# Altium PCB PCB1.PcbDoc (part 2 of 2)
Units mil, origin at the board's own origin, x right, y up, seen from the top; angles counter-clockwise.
Board outline 3035 x 2265 mil, 2 copper layers (Top Layer, Bottom Layer); 66 components, 70 nets, 274 pads, 24 vias.
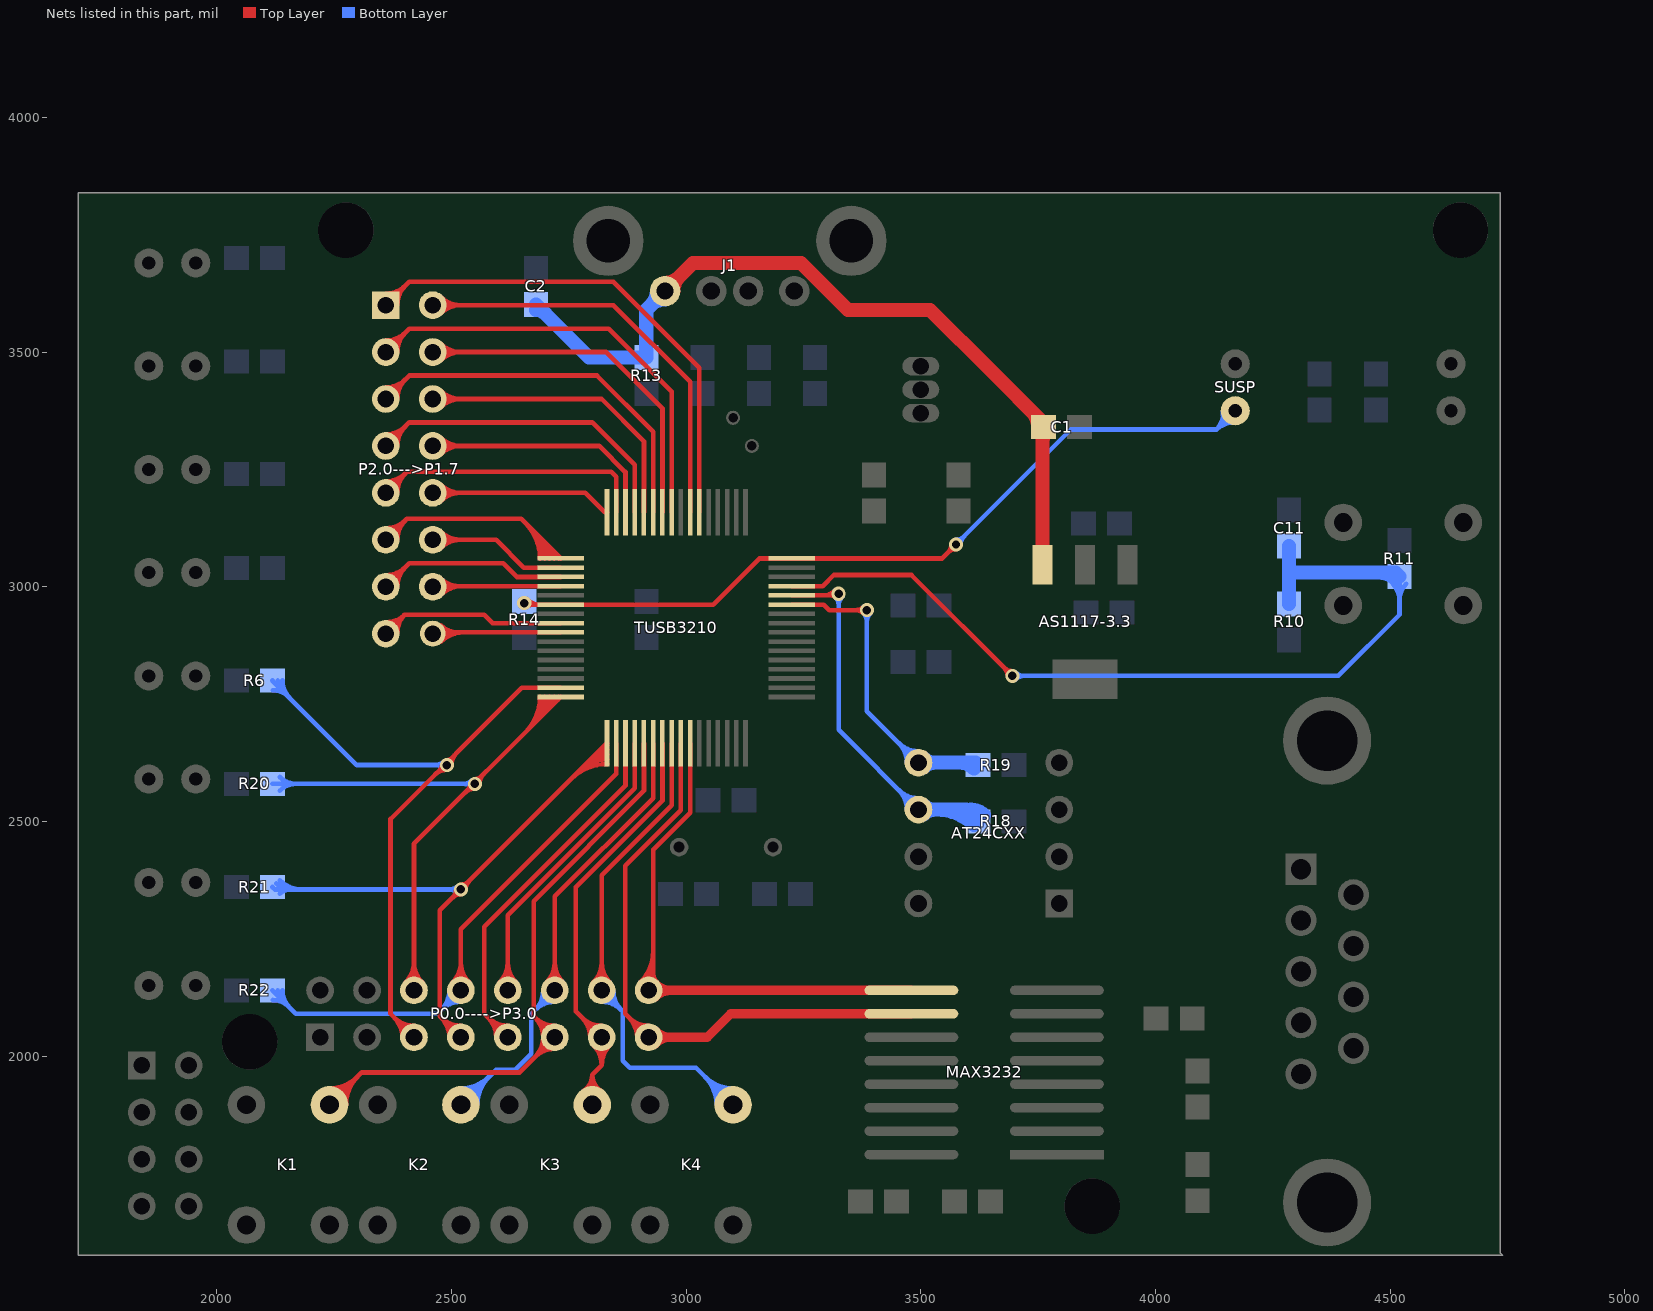
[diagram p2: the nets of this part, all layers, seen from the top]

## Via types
v1: diameter 30, hole 18, Top Layer to Bottom Layer, 24 vias

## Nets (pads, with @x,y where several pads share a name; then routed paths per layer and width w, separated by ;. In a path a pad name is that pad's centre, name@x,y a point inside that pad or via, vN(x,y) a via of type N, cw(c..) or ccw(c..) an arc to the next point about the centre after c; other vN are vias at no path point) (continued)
P0_4: P0.0---->P3.0.5 R6.1 TUSB3210.47 | length 2282.5
  Top Layer w10: P0.0---->P3.0.5@2420,2040 2370,2090 2370,2505 2649.68,2784.68 TUSB3210.47@2732.87,2784.68 ; 2378.13,2081.87 cw(c2336.26,2040) P0.0---->P3.0.5@2395.47,2040 ; 2378.13,2081.87 ccw(c2420,2123.74) P0.0---->P3.0.5@2420,2064.53 ; 2378.13,2081.87 cw(c2336.26,2040) P0.0---->P3.0.5@2395.47,2040 ; 2378.13,2081.87 ccw(c2420,2123.74) P0.0---->P3.0.5@2420,2064.53 ; 2378.13,2081.87 ccw(c2420,2123.74) P0.0---->P3.0.5@2420,2064.53 ; 2378.13,2081.87 cw(c2336.26,2040) P0.0---->P3.0.5@2395.47,2040 ; 2395.2,2064.8 cw(c2370.4,2040) P0.0---->P3.0.5@2405.47,2040 ; 2395.2,2064.8 ccw(c2420,2089.6) P0.0---->P3.0.5@2420,2054.53 ; 2395.2,2064.8 cw(c2370.4,2040) P0.0---->P3.0.5@2405.47,2040 ; 2395.2,2064.8 ccw(c2420,2089.6) P0.0---->P3.0.5@2420,2054.53 ; 2395.2,2064.8 ccw(c2420,2089.6) P0.0---->P3.0.5@2420,2054.53 ; 2395.2,2064.8 cw(c2370.4,2040) P0.0---->P3.0.5@2405.47,2040 ; 2464.39,2599.39 cw(c2490,2573.79) 2490,2610 ccw(c2490,2573.79) 2464.39,2599.39 ; 2476.46,2611.46 ccw(c2467.93,2620) 2480,2620 cw(c2467.93,2620) 2476.46,2611.46 ; v1@2490,2630 ccw(c2490,2642.07) 2498.54,2633.54 cw(c2490,2642.07) v1@2490,2630 ; v1@2500,2620 cw(c2536.21,2620) 2510.61,2645.61 ccw(c2536.21,2620) v1@2500,2620
  Bottom Layer w10: R6.1@2118.39,2800 2298.39,2620 v1(2490,2620) ; 2465.86,2620 cw(c2465.86,2595.86) 2482.93,2612.93 ccw(c2465.86,2595.86) 2465.86,2620 ; 2465.86,2620 ccw(c2465.86,2644.14) 2482.93,2627.07 cw(c2465.86,2644.14) 2465.86,2620 ; R6.1@2119.37,2779.41 cw(c2119.37,2732.08) 2152.84,2765.55 ccw(c2119.37,2732.08) R6.1@2119.37,2779.41 ; R6.1@2129.96,2800 ccw(c2157.91,2800) 2138.15,2780.24 cw(c2157.91,2800) R6.1@2129.96,2800 ; R6.1@2139.96,2800 ccw(c2192.05,2800) 2155.22,2763.17 cw(c2192.05,2800) R6.1@2139.96,2800
P0_5: P0.0---->P3.0.6 R20.1 TUSB3210.48 | length 2702.9
  Top Layer w10: P0.0---->P3.0.6@2420,2140 2420,2452.13 TUSB3210.48@2732.87,2765 ; P0.0---->P3.0.6@2402.66,2157.34 ccw(c2360.79,2199.21) 2420,2199.21 ; P0.0---->P3.0.6@2402.66,2157.34 ccw(c2360.79,2199.21) 2420,2199.21 ; P0.0---->P3.0.6@2402.66,2157.34 ccw(c2360.79,2199.21) 2420,2199.21 ; P0.0---->P3.0.6@2409.73,2150.27 ccw(c2384.93,2175.07) 2420,2175.07 ; P0.0---->P3.0.6@2409.73,2150.27 ccw(c2384.93,2175.07) 2420,2175.07 ; P0.0---->P3.0.6@2409.73,2150.27 ccw(c2384.93,2175.07) 2420,2175.07 ; 2420,2175.07 ccw(c2455.07,2175.07) P0.0---->P3.0.6@2430.27,2150.27 ; 2420,2175.07 ccw(c2455.07,2175.07) P0.0---->P3.0.6@2430.27,2150.27 ; 2420,2175.07 ccw(c2455.07,2175.07) P0.0---->P3.0.6@2430.27,2150.27 ; 2420,2199.21 ccw(c2479.21,2199.21) P0.0---->P3.0.6@2437.34,2157.34 ; 2420,2199.21 ccw(c2479.21,2199.21) P0.0---->P3.0.6@2437.34,2157.34 ; 2420,2199.21 ccw(c2479.21,2199.21) P0.0---->P3.0.6@2437.34,2157.34 ; 2657.4,2689.52 ccw(c2581.92,2765) TUSB3210.48@2688.66,2765 ; 2657.4,2689.52 ccw(c2581.92,2765) TUSB3210.48@2688.66,2765 ; 2657.4,2689.52 ccw(c2581.92,2765) TUSB3210.48@2688.66,2765 ; 2674.47,2706.6 ccw(c2616.07,2765) TUSB3210.48@2698.66,2765 ; 2674.47,2706.6 ccw(c2616.07,2765) TUSB3210.48@2698.66,2765 ; 2674.47,2706.6 ccw(c2616.07,2765) TUSB3210.48@2698.66,2765 ; 2691.54,2723.67 ccw(c2650.21,2765) TUSB3210.48@2708.66,2765 ; 2691.54,2723.67 ccw(c2650.21,2765) TUSB3210.48@2708.66,2765 ; 2691.54,2723.67 ccw(c2650.21,2765) TUSB3210.48@2708.66,2765 ; 2708.61,2740.74 ccw(c2684.35,2765) TUSB3210.48@2718.66,2765 ; 2708.61,2740.74 ccw(c2684.35,2765) TUSB3210.48@2718.66,2765 ; 2708.61,2740.74 ccw(c2684.35,2765) TUSB3210.48@2718.66,2765 ; 2725.68,2757.81 ccw(c2718.49,2765) TUSB3210.48@2728.66,2765 ; 2725.68,2757.81 ccw(c2718.49,2765) TUSB3210.48@2728.66,2765 ; 2725.68,2757.81 ccw(c2718.49,2765) TUSB3210.48@2728.66,2765 ; 2529.3,2561.43 cw(c2550,2540.73) 2550,2570 ccw(c2550,2540.73) 2529.3,2561.43 ; 2534.43,2566.56 ccw(c2520.99,2580) 2540,2580 cw(c2520.99,2580) 2534.43,2566.56 ; v1@2550,2590 ccw(c2550,2609.01) 2563.44,2595.57 cw(c2550,2609.01) v1@2550,2590 ; v1@2560,2580 cw(c2589.27,2580) 2568.57,2600.7 ccw(c2589.27,2580) v1@2560,2580
  Bottom Layer w10: R20.1@2118.39,2580 v1(2550,2580) ; 2169.08,2580 cw(c2169.08,2629.71) 2133.93,2594.56 ccw(c2169.08,2629.71) 2169.08,2580 ; 2169.08,2580 ccw(c2169.08,2530.29) 2133.93,2565.44 cw(c2169.08,2530.29) 2169.08,2580 ; 2525.86,2580 cw(c2525.86,2555.86) 2542.93,2572.93 ccw(c2525.86,2555.86) 2525.86,2580 ; 2525.86,2580 ccw(c2525.86,2604.14) 2542.93,2587.07 cw(c2525.86,2604.14) 2525.86,2580
P0_6: P0.0---->P3.0.7 R21.1 TUSB3210.49 | length 2780.1
  Top Layer w10: P0.0---->P3.0.7@2520,2040 2475,2085 2475,2310.28 TUSB3210.49@2831.3,2666.57 ; 2478.13,2081.87 cw(c2436.26,2040) P0.0---->P3.0.7@2495.47,2040 ; 2478.13,2081.87 ccw(c2520,2123.74) P0.0---->P3.0.7@2520,2064.53 ; 2478.13,2081.87 cw(c2436.26,2040) P0.0---->P3.0.7@2495.47,2040 ; 2478.13,2081.87 ccw(c2520,2123.74) P0.0---->P3.0.7@2520,2064.53 ; 2478.13,2081.87 ccw(c2520,2123.74) P0.0---->P3.0.7@2520,2064.53 ; 2478.13,2081.87 cw(c2436.26,2040) P0.0---->P3.0.7@2495.47,2040 ; 2495.2,2064.8 cw(c2470.4,2040) P0.0---->P3.0.7@2505.47,2040 ; 2495.2,2064.8 ccw(c2520,2089.6) P0.0---->P3.0.7@2520,2054.53 ; 2495.2,2064.8 cw(c2470.4,2040) P0.0---->P3.0.7@2505.47,2040 ; 2495.2,2064.8 ccw(c2520,2089.6) P0.0---->P3.0.7@2520,2054.53 ; 2495.2,2064.8 ccw(c2520,2089.6) P0.0---->P3.0.7@2520,2054.53 ; 2495.2,2064.8 cw(c2470.4,2040) P0.0---->P3.0.7@2505.47,2040 ; 2755.82,2591.1 cw(c2831.3,2515.62) TUSB3210.49@2831.3,2622.36 ; 2755.82,2591.1 cw(c2831.3,2515.62) TUSB3210.49@2831.3,2622.36 ; 2755.82,2591.1 cw(c2831.3,2515.62) TUSB3210.49@2831.3,2622.36 ; 2772.9,2608.17 cw(c2831.3,2549.77) TUSB3210.49@2831.3,2632.36 ; 2772.9,2608.17 cw(c2831.3,2549.77) TUSB3210.49@2831.3,2632.36 ; 2772.9,2608.17 cw(c2831.3,2549.77) TUSB3210.49@2831.3,2632.36 ; 2789.97,2625.24 cw(c2831.3,2583.91) TUSB3210.49@2831.3,2642.36 ; 2789.97,2625.24 cw(c2831.3,2583.91) TUSB3210.49@2831.3,2642.36 ; 2789.97,2625.24 cw(c2831.3,2583.91) TUSB3210.49@2831.3,2642.36 ; 2807.04,2642.31 cw(c2831.3,2618.05) TUSB3210.49@2831.3,2652.36 ; 2807.04,2642.31 cw(c2831.3,2618.05) TUSB3210.49@2831.3,2652.36 ; 2807.04,2642.31 cw(c2831.3,2618.05) TUSB3210.49@2831.3,2652.36 ; 2824.11,2659.38 cw(c2831.3,2652.19) TUSB3210.49@2831.3,2662.36 ; 2824.11,2659.38 cw(c2831.3,2652.19) TUSB3210.49@2831.3,2662.36 ; 2824.11,2659.38 cw(c2831.3,2652.19) TUSB3210.49@2831.3,2662.36 ; 2502.46,2337.73 cw(c2520,2320.19) 2520,2345 ccw(c2520,2320.19) 2502.46,2337.73 ; 2503.12,2338.4 ccw(c2486.52,2355) 2510,2355 cw(c2486.52,2355) 2503.12,2338.4 ; v1@2520,2365 ccw(c2520,2388.48) 2536.6,2371.88 cw(c2520,2388.48) v1@2520,2365 ; v1@2530,2355 cw(c2554.81,2355) 2537.27,2372.54 ccw(c2554.81,2355) v1@2530,2355
  Bottom Layer w10: R21.1@2118.39,2360 2123.39,2355 v1(2520,2355) ; 2157.01,2355 cw(c2157.01,2397.64) 2126.86,2367.49 ccw(c2157.01,2397.64) 2157.01,2355 ; 2157.01,2355 ccw(c2157.01,2322.36) 2133.93,2345.44 cw(c2157.01,2322.36) 2157.01,2355 ; 2495.86,2355 cw(c2495.86,2330.86) 2512.93,2347.93 ccw(c2495.86,2330.86) 2495.86,2355 ; 2495.86,2355 ccw(c2495.86,2379.14) 2512.93,2362.07 cw(c2495.86,2379.14) 2495.86,2355 ; R21.1@2133.93,2374.56 ccw(c2181.15,2421.78) 2181.15,2355 cw(c2181.15,2421.78) R21.1@2133.93,2374.56
P0_7: P0.0---->P3.0.8 R22.1 TUSB3210.50 | length 2047.3
  Top Layer w10: P0.0---->P3.0.8@2520,2140 2520,2270 2850.98,2600.98 TUSB3210.50@2850.98,2666.57 ; P0.0---->P3.0.8@2502.66,2157.34 ccw(c2460.79,2199.21) 2520,2199.21 ; P0.0---->P3.0.8@2502.66,2157.34 ccw(c2460.79,2199.21) 2520,2199.21 ; P0.0---->P3.0.8@2502.66,2157.34 ccw(c2460.79,2199.21) 2520,2199.21 ; P0.0---->P3.0.8@2509.73,2150.27 ccw(c2484.93,2175.07) 2520,2175.07 ; P0.0---->P3.0.8@2509.73,2150.27 ccw(c2484.93,2175.07) 2520,2175.07 ; P0.0---->P3.0.8@2509.73,2150.27 ccw(c2484.93,2175.07) 2520,2175.07 ; 2520,2175.07 ccw(c2555.07,2175.07) P0.0---->P3.0.8@2530.27,2150.27 ; 2520,2175.07 ccw(c2555.07,2175.07) P0.0---->P3.0.8@2530.27,2150.27 ; 2520,2175.07 ccw(c2555.07,2175.07) P0.0---->P3.0.8@2530.27,2150.27 ; 2520,2199.21 ccw(c2579.21,2199.21) P0.0---->P3.0.8@2537.34,2157.34 ; 2520,2199.21 ccw(c2579.21,2199.21) P0.0---->P3.0.8@2537.34,2157.34 ; 2520,2199.21 ccw(c2579.21,2199.21) P0.0---->P3.0.8@2537.34,2157.34
  Bottom Layer w10: R22.1@2118.39,2140 2168.39,2090 2470,2090 P0.0---->P3.0.8@2520,2140 ; 2478.13,2098.13 cw(c2520,2056.26) 2520,2115.47 ccw(c2520,2056.26) 2478.13,2098.13 ; 2478.13,2098.13 ccw(c2436.26,2140) 2495.47,2140 cw(c2436.26,2140) 2478.13,2098.13 ; 2495.2,2115.2 cw(c2520,2090.4) 2520,2125.47 ccw(c2520,2090.4) 2495.2,2115.2 ; 2495.2,2115.2 ccw(c2470.4,2140) 2505.47,2140 cw(c2470.4,2140) 2495.2,2115.2 ; R22.1@2119.37,2119.41 cw(c2119.37,2072.08) 2152.84,2105.55 ccw(c2119.37,2072.08) R22.1@2119.37,2119.41 ; R22.1@2129.96,2140 ccw(c2157.91,2140) 2138.15,2120.24 cw(c2157.91,2140) R22.1@2129.96,2140 ; R22.1@2139.96,2140 ccw(c2192.05,2140) 2155.22,2103.17 cw(c2192.05,2140) R22.1@2139.96,2140
P1_0: P2.0--->P1.7.9 TUSB3210.31 | length 1033.8
  Top Layer w10: P2.0--->P1.7.9@2360,3200 2405,3245 2840,3245 2850.98,3234.02 TUSB3210.31@2850.98,3158.7 ; P2.0--->P1.7.9@2360,3214.53 ccw(c2360,3249.6) 2384.8,3224.8 ; P2.0--->P1.7.9@2360,3214.53 ccw(c2360,3249.6) 2384.8,3224.8 ; P2.0--->P1.7.9@2360,3214.53 ccw(c2360,3249.6) 2384.8,3224.8 ; P2.0--->P1.7.9@2360,3224.53 ccw(c2360,3283.74) 2401.87,3241.87 ; P2.0--->P1.7.9@2360,3224.53 ccw(c2360,3283.74) 2401.87,3241.87 ; P2.0--->P1.7.9@2360,3224.53 ccw(c2360,3283.74) 2401.87,3241.87 ; P2.0--->P1.7.9@2374.53,3200 cw(c2409.6,3200) 2384.8,3224.8 ; P2.0--->P1.7.9@2374.53,3200 cw(c2409.6,3200) 2384.8,3224.8 ; P2.0--->P1.7.9@2374.53,3200 cw(c2409.6,3200) 2384.8,3224.8 ; P2.0--->P1.7.9@2384.53,3200 cw(c2443.74,3200) 2401.87,3241.87 ; P2.0--->P1.7.9@2384.53,3200 cw(c2443.74,3200) 2401.87,3241.87 ; P2.0--->P1.7.9@2384.53,3200 cw(c2443.74,3200) 2401.87,3241.87
P1_1: P2.0--->P1.7.10 TUSB3210.32 | length 832.7
  Top Layer w10: P2.0--->P1.7.10@2460,3200 2785,3200 2826.3,3158.7 TUSB3210.32@2831.3,3158.7 ; P2.0--->P1.7.10@2470.27,3189.73 cw(c2495.07,3164.93) 2495.07,3200 ; P2.0--->P1.7.10@2470.27,3189.73 cw(c2495.07,3164.93) 2495.07,3200 ; P2.0--->P1.7.10@2470.27,3189.73 cw(c2495.07,3164.93) 2495.07,3200 ; P2.0--->P1.7.10@2470.27,3210.27 ccw(c2495.07,3235.07) 2495.07,3200 ; P2.0--->P1.7.10@2470.27,3210.27 ccw(c2495.07,3235.07) 2495.07,3200 ; P2.0--->P1.7.10@2470.27,3210.27 ccw(c2495.07,3235.07) 2495.07,3200 ; P2.0--->P1.7.10@2477.34,3182.66 cw(c2519.21,3140.79) 2519.21,3200 ; P2.0--->P1.7.10@2477.34,3182.66 cw(c2519.21,3140.79) 2519.21,3200 ; P2.0--->P1.7.10@2477.34,3182.66 cw(c2519.21,3140.79) 2519.21,3200 ; P2.0--->P1.7.10@2477.34,3217.34 ccw(c2519.21,3259.21) 2519.21,3200 ; P2.0--->P1.7.10@2477.34,3217.34 ccw(c2519.21,3259.21) 2519.21,3200 ; P2.0--->P1.7.10@2477.34,3217.34 ccw(c2519.21,3259.21) 2519.21,3200
P1_2: P2.0--->P1.7.11 TUSB3210.33 | length 1559.6
  Top Layer w10: P2.0--->P1.7.11@2360,3100 2405,3145 2648.15,3145 TUSB3210.33@2732.87,3060.28 ; P2.0--->P1.7.11@2360,3114.53 ccw(c2360,3149.6) 2384.8,3124.8 ; P2.0--->P1.7.11@2360,3114.53 ccw(c2360,3149.6) 2384.8,3124.8 ; P2.0--->P1.7.11@2360,3114.53 ccw(c2360,3149.6) 2384.8,3124.8 ; P2.0--->P1.7.11@2360,3124.53 ccw(c2360,3183.74) 2401.87,3141.87 ; P2.0--->P1.7.11@2360,3124.53 ccw(c2360,3183.74) 2401.87,3141.87 ; P2.0--->P1.7.11@2360,3124.53 ccw(c2360,3183.74) 2401.87,3141.87 ; P2.0--->P1.7.11@2374.53,3100 cw(c2409.6,3100) 2384.8,3124.8 ; P2.0--->P1.7.11@2374.53,3100 cw(c2409.6,3100) 2384.8,3124.8 ; P2.0--->P1.7.11@2374.53,3100 cw(c2409.6,3100) 2384.8,3124.8 ; P2.0--->P1.7.11@2384.53,3100 cw(c2443.74,3100) 2401.87,3141.87 ; P2.0--->P1.7.11@2384.53,3100 cw(c2443.74,3100) 2401.87,3141.87 ; P2.0--->P1.7.11@2384.53,3100 cw(c2443.74,3100) 2401.87,3141.87 ; 2657.4,3135.75 cw(c2581.92,3060.28) TUSB3210.33@2688.66,3060.28 ; 2657.4,3135.75 cw(c2581.92,3060.28) TUSB3210.33@2688.66,3060.28 ; 2657.4,3135.75 cw(c2581.92,3060.28) TUSB3210.33@2688.66,3060.28 ; 2674.47,3118.68 cw(c2616.07,3060.28) TUSB3210.33@2698.66,3060.28 ; 2674.47,3118.68 cw(c2616.07,3060.28) TUSB3210.33@2698.66,3060.28 ; 2674.47,3118.68 cw(c2616.07,3060.28) TUSB3210.33@2698.66,3060.28 ; 2691.54,3101.61 cw(c2650.21,3060.28) TUSB3210.33@2708.66,3060.28 ; 2691.54,3101.61 cw(c2650.21,3060.28) TUSB3210.33@2708.66,3060.28 ; 2691.54,3101.61 cw(c2650.21,3060.28) TUSB3210.33@2708.66,3060.28 ; 2708.61,3084.54 cw(c2684.35,3060.28) TUSB3210.33@2718.66,3060.28 ; 2708.61,3084.54 cw(c2684.35,3060.28) TUSB3210.33@2718.66,3060.28 ; 2708.61,3084.54 cw(c2684.35,3060.28) TUSB3210.33@2718.66,3060.28 ; 2725.68,3067.47 cw(c2718.49,3060.28) TUSB3210.33@2728.66,3060.28 ; 2725.68,3067.47 cw(c2718.49,3060.28) TUSB3210.33@2728.66,3060.28 ; 2725.68,3067.47 cw(c2718.49,3060.28) TUSB3210.33@2728.66,3060.28
P1_3: P2.0--->P1.7.12 TUSB3210.34 | length 741.8
  Top Layer w10: P2.0--->P1.7.12@2460,3100 2595,3100 2654.41,3040.59 TUSB3210.34@2732.87,3040.59 ; P2.0--->P1.7.12@2470.27,3089.73 cw(c2495.07,3064.93) 2495.07,3100 ; P2.0--->P1.7.12@2470.27,3089.73 cw(c2495.07,3064.93) 2495.07,3100 ; P2.0--->P1.7.12@2470.27,3089.73 cw(c2495.07,3064.93) 2495.07,3100 ; P2.0--->P1.7.12@2470.27,3110.27 ccw(c2495.07,3135.07) 2495.07,3100 ; P2.0--->P1.7.12@2470.27,3110.27 ccw(c2495.07,3135.07) 2495.07,3100 ; P2.0--->P1.7.12@2470.27,3110.27 ccw(c2495.07,3135.07) 2495.07,3100 ; P2.0--->P1.7.12@2477.34,3082.66 cw(c2519.21,3040.79) 2519.21,3100 ; P2.0--->P1.7.12@2477.34,3082.66 cw(c2519.21,3040.79) 2519.21,3100 ; P2.0--->P1.7.12@2477.34,3082.66 cw(c2519.21,3040.79) 2519.21,3100 ; P2.0--->P1.7.12@2477.34,3117.34 ccw(c2519.21,3159.21) 2519.21,3100 ; P2.0--->P1.7.12@2477.34,3117.34 ccw(c2519.21,3159.21) 2519.21,3100 ; P2.0--->P1.7.12@2477.34,3117.34 ccw(c2519.21,3159.21) 2519.21,3100
P1_4: P2.0--->P1.7.13 TUSB3210.35 | length 850
  Top Layer w10: P2.0--->P1.7.13@2360,3000 2410,3050 2610,3050 2639.09,3020.91 TUSB3210.35@2732.87,3020.91 ; P2.0--->P1.7.13@2360,3014.53 ccw(c2360,3049.6) 2384.8,3024.8 ; P2.0--->P1.7.13@2360,3014.53 ccw(c2360,3049.6) 2384.8,3024.8 ; P2.0--->P1.7.13@2360,3014.53 ccw(c2360,3049.6) 2384.8,3024.8 ; P2.0--->P1.7.13@2360,3024.53 ccw(c2360,3083.74) 2401.87,3041.87 ; P2.0--->P1.7.13@2360,3024.53 ccw(c2360,3083.74) 2401.87,3041.87 ; P2.0--->P1.7.13@2360,3024.53 ccw(c2360,3083.74) 2401.87,3041.87 ; P2.0--->P1.7.13@2374.53,3000 cw(c2409.6,3000) 2384.8,3024.8 ; P2.0--->P1.7.13@2374.53,3000 cw(c2409.6,3000) 2384.8,3024.8 ; P2.0--->P1.7.13@2374.53,3000 cw(c2409.6,3000) 2384.8,3024.8 ; P2.0--->P1.7.13@2384.53,3000 cw(c2443.74,3000) 2401.87,3041.87 ; P2.0--->P1.7.13@2384.53,3000 cw(c2443.74,3000) 2401.87,3041.87 ; P2.0--->P1.7.13@2384.53,3000 cw(c2443.74,3000) 2401.87,3041.87
P1_5: P2.0--->P1.7.14 TUSB3210.36 | length 717.7
  Top Layer w10: P2.0--->P1.7.14@2460,3000 2461.22,3001.22 TUSB3210.36@2732.87,3001.22 ; P2.0--->P1.7.14@2470.27,2989.73 cw(c2498.02,2961.98) 2498.02,3001.22 ; P2.0--->P1.7.14@2470.27,2989.73 cw(c2498.02,2961.98) 2498.02,3001.22 ; P2.0--->P1.7.14@2470.27,2989.73 cw(c2498.02,2961.98) 2498.02,3001.22 ; P2.0--->P1.7.14@2470.27,3010.27 ccw(c2492.13,3032.13) 2492.13,3001.22 ; P2.0--->P1.7.14@2470.27,3010.27 ccw(c2492.13,3032.13) 2492.13,3001.22 ; P2.0--->P1.7.14@2470.27,3010.27 ccw(c2492.13,3032.13) 2492.13,3001.22 ; P2.0--->P1.7.14@2477.34,2982.66 cw(c2522.16,2937.84) 2522.16,3001.22 ; P2.0--->P1.7.14@2477.34,2982.66 cw(c2522.16,2937.84) 2522.16,3001.22 ; P2.0--->P1.7.14@2477.34,2982.66 cw(c2522.16,2937.84) 2522.16,3001.22 ; P2.0--->P1.7.14@2477.34,3017.34 ccw(c2516.27,3056.27) 2516.27,3001.22 ; P2.0--->P1.7.14@2477.34,3017.34 ccw(c2516.27,3056.27) 2516.27,3001.22 ; P2.0--->P1.7.14@2477.34,3017.34 ccw(c2516.27,3056.27) 2516.27,3001.22
P1_6: P2.0--->P1.7.15 TUSB3210.40 | length 534.7
  Top Layer w10: P2.0--->P1.7.15@2360,2900 2400,2940 ; P2.0--->P1.7.15@2360.48,2914.52 ccw(c2361.51,2945.87) 2383.69,2923.69 ccw(c2405.87,2901.51) P2.0--->P1.7.15@2374.52,2900.48 ; P2.0--->P1.7.15@2360.81,2924.51 ccw(c2362.55,2977.45) 2400,2940 ; P2.0--->P1.7.15@2384.51,2900.81 cw(c2437.45,2902.55) 2400,2940 ; TUSB3210.40@2732.87,2922.48 2587.48,2922.48 2569.96,2940 2400,2940
P1_7: P2.0--->P1.7.16 TUSB3210.41 | length 646.7
  Top Layer w10: P2.0--->P1.7.16@2460,2900 2462.8,2902.8 TUSB3210.41@2732.87,2902.8 ; P2.0--->P1.7.16@2468.84,2891.16 cw(c2496.93,2863.07) 2496.93,2902.8 ; P2.0--->P1.7.16@2475.91,2884.09 cw(c2521.07,2838.93) 2521.07,2902.8 ; P2.0--->P1.7.16@2475.91,2915.91 ccw(c2507.57,2947.57) 2507.57,2902.8 ; P2.0--->P1.7.16@2470.27,2889.73 cw(c2501.82,2858.18) 2501.82,2902.8 ccw(c2501.82,2858.18) P2.0--->P1.7.16@2470.27,2889.73 ; P2.0--->P1.7.16@2477.34,2882.66 cw(c2525.96,2834.04) 2525.96,2902.8 ccw(c2525.96,2834.04) P2.0--->P1.7.16@2477.34,2882.66 ; P2.0--->P1.7.16@2477.34,2917.34 ccw(c2512.47,2952.47) 2512.47,2902.8 cw(c2512.47,2952.47) P2.0--->P1.7.16@2477.34,2917.34
P2_0: P2.0--->P1.7.1 TUSB3210.22 | length 1517.2
  Top Layer w10: P2.0--->P1.7.1@2360,3600 2410,3650 2845,3650 3028.15,3466.85 TUSB3210.22@3028.15,3158.7 ; P2.0--->P1.7.1@2360,3614.53 ccw(c2360,3649.6) P2.0--->P1.7.1@2384.8,3624.8 ; P2.0--->P1.7.1@2360,3614.53 ccw(c2360,3649.6) P2.0--->P1.7.1@2384.8,3624.8 ; P2.0--->P1.7.1@2360,3614.53 ccw(c2360,3649.6) P2.0--->P1.7.1@2384.8,3624.8 ; P2.0--->P1.7.1@2360,3624.53 ccw(c2360,3683.74) 2401.87,3641.87 ; P2.0--->P1.7.1@2360,3624.53 ccw(c2360,3683.74) 2401.87,3641.87 ; P2.0--->P1.7.1@2360,3624.53 ccw(c2360,3683.74) 2401.87,3641.87 ; P2.0--->P1.7.1@2374.53,3600 cw(c2409.6,3600) P2.0--->P1.7.1@2384.8,3624.8 ; P2.0--->P1.7.1@2374.53,3600 cw(c2409.6,3600) P2.0--->P1.7.1@2384.8,3624.8 ; P2.0--->P1.7.1@2374.53,3600 cw(c2409.6,3600) P2.0--->P1.7.1@2384.8,3624.8 ; P2.0--->P1.7.1@2384.53,3600 cw(c2443.74,3600) 2401.87,3641.87 ; P2.0--->P1.7.1@2384.53,3600 cw(c2443.74,3600) 2401.87,3641.87 ; P2.0--->P1.7.1@2384.53,3600 cw(c2443.74,3600) 2401.87,3641.87
P2_1: P2.0--->P1.7.2 TUSB3210.23 | length 1338.3
  Top Layer w10: P2.0--->P1.7.2@2460,3600 2845,3600 3008.46,3436.54 TUSB3210.23@3008.46,3158.7 ; P2.0--->P1.7.2@2470.27,3589.73 cw(c2495.07,3564.93) 2495.07,3600 ; P2.0--->P1.7.2@2470.27,3589.73 cw(c2495.07,3564.93) 2495.07,3600 ; P2.0--->P1.7.2@2470.27,3589.73 cw(c2495.07,3564.93) 2495.07,3600 ; P2.0--->P1.7.2@2470.27,3610.27 ccw(c2495.07,3635.07) 2495.07,3600 ; P2.0--->P1.7.2@2470.27,3610.27 ccw(c2495.07,3635.07) 2495.07,3600 ; P2.0--->P1.7.2@2470.27,3610.27 ccw(c2495.07,3635.07) 2495.07,3600 ; P2.0--->P1.7.2@2477.34,3582.66 cw(c2519.21,3540.79) 2519.21,3600 ; P2.0--->P1.7.2@2477.34,3582.66 cw(c2519.21,3540.79) 2519.21,3600 ; P2.0--->P1.7.2@2477.34,3582.66 cw(c2519.21,3540.79) 2519.21,3600 ; P2.0--->P1.7.2@2477.34,3617.34 ccw(c2519.21,3659.21) 2519.21,3600 ; P2.0--->P1.7.2@2477.34,3617.34 ccw(c2519.21,3659.21) 2519.21,3600 ; P2.0--->P1.7.2@2477.34,3617.34 ccw(c2519.21,3659.21) 2519.21,3600
P2_2: P2.0--->P1.7.3 TUSB3210.25 | length 1386.9
  Top Layer w10: P2.0--->P1.7.3@2360,3500 2410,3550 2835,3550 2969.09,3415.91 TUSB3210.25@2969.09,3158.7 ; P2.0--->P1.7.3@2360,3514.53 ccw(c2360,3549.6) 2384.8,3524.8 ; P2.0--->P1.7.3@2360,3514.53 ccw(c2360,3549.6) 2384.8,3524.8 ; P2.0--->P1.7.3@2360,3514.53 ccw(c2360,3549.6) 2384.8,3524.8 ; P2.0--->P1.7.3@2360,3524.53 ccw(c2360,3583.74) 2401.87,3541.87 ; P2.0--->P1.7.3@2360,3524.53 ccw(c2360,3583.74) 2401.87,3541.87 ; P2.0--->P1.7.3@2360,3524.53 ccw(c2360,3583.74) 2401.87,3541.87 ; P2.0--->P1.7.3@2374.53,3500 cw(c2409.6,3500) 2384.8,3524.8 ; P2.0--->P1.7.3@2374.53,3500 cw(c2409.6,3500) 2384.8,3524.8 ; P2.0--->P1.7.3@2374.53,3500 cw(c2409.6,3500) 2384.8,3524.8 ; P2.0--->P1.7.3@2384.53,3500 cw(c2443.74,3500) 2401.87,3541.87 ; P2.0--->P1.7.3@2384.53,3500 cw(c2443.74,3500) 2401.87,3541.87 ; P2.0--->P1.7.3@2384.53,3500 cw(c2443.74,3500) 2401.87,3541.87
P2_3: P2.0--->P1.7.4 TUSB3210.26 | length 1205.1
  Top Layer w10: P2.0--->P1.7.4@2460,3500 2830,3500 2949.41,3380.59 TUSB3210.26@2949.41,3158.7 ; P2.0--->P1.7.4@2470.27,3489.73 cw(c2495.07,3464.93) 2495.07,3500 ; P2.0--->P1.7.4@2470.27,3489.73 cw(c2495.07,3464.93) 2495.07,3500 ; P2.0--->P1.7.4@2470.27,3489.73 cw(c2495.07,3464.93) 2495.07,3500 ; P2.0--->P1.7.4@2470.27,3510.27 ccw(c2495.07,3535.07) 2495.07,3500 ; P2.0--->P1.7.4@2470.27,3510.27 ccw(c2495.07,3535.07) 2495.07,3500 ; P2.0--->P1.7.4@2470.27,3510.27 ccw(c2495.07,3535.07) 2495.07,3500 ; P2.0--->P1.7.4@2477.34,3482.66 cw(c2519.21,3440.79) 2519.21,3500 ; P2.0--->P1.7.4@2477.34,3482.66 cw(c2519.21,3440.79) 2519.21,3500 ; P2.0--->P1.7.4@2477.34,3482.66 cw(c2519.21,3440.79) 2519.21,3500 ; P2.0--->P1.7.4@2477.34,3517.34 ccw(c2519.21,3559.21) 2519.21,3500 ; P2.0--->P1.7.4@2477.34,3517.34 ccw(c2519.21,3559.21) 2519.21,3500 ; P2.0--->P1.7.4@2477.34,3517.34 ccw(c2519.21,3559.21) 2519.21,3500
P2_4: P2.0--->P1.7.5 TUSB3210.27 | length 1255.9
  Top Layer w10: P2.0--->P1.7.5@2360,3400 2410,3450 2810,3450 2929.72,3330.28 TUSB3210.27@2929.72,3158.7 ; P2.0--->P1.7.5@2360,3414.53 ccw(c2360,3449.6) 2384.8,3424.8 ; P2.0--->P1.7.5@2360,3414.53 ccw(c2360,3449.6) 2384.8,3424.8 ; P2.0--->P1.7.5@2360,3414.53 ccw(c2360,3449.6) 2384.8,3424.8 ; P2.0--->P1.7.5@2360,3424.53 ccw(c2360,3483.74) 2401.87,3441.87 ; P2.0--->P1.7.5@2360,3424.53 ccw(c2360,3483.74) 2401.87,3441.87 ; P2.0--->P1.7.5@2360,3424.53 ccw(c2360,3483.74) 2401.87,3441.87 ; P2.0--->P1.7.5@2374.53,3400 cw(c2409.6,3400) 2384.8,3424.8 ; P2.0--->P1.7.5@2374.53,3400 cw(c2409.6,3400) 2384.8,3424.8 ; P2.0--->P1.7.5@2374.53,3400 cw(c2409.6,3400) 2384.8,3424.8 ; P2.0--->P1.7.5@2384.53,3400 cw(c2443.74,3400) 2401.87,3441.87 ; P2.0--->P1.7.5@2384.53,3400 cw(c2443.74,3400) 2401.87,3441.87 ; P2.0--->P1.7.5@2384.53,3400 cw(c2443.74,3400) 2401.87,3441.87
P2_5: P2.0--->P1.7.6 TUSB3210.28 | length 1082.9
  Top Layer w10: P2.0--->P1.7.6@2460,3400 2820,3400 2910.04,3309.96 TUSB3210.28@2910.04,3158.7 ; P2.0--->P1.7.6@2470.27,3389.73 cw(c2495.07,3364.93) 2495.07,3400 ; P2.0--->P1.7.6@2470.27,3389.73 cw(c2495.07,3364.93) 2495.07,3400 ; P2.0--->P1.7.6@2470.27,3389.73 cw(c2495.07,3364.93) 2495.07,3400 ; P2.0--->P1.7.6@2470.27,3410.27 ccw(c2495.07,3435.07) 2495.07,3400 ; P2.0--->P1.7.6@2470.27,3410.27 ccw(c2495.07,3435.07) 2495.07,3400 ; P2.0--->P1.7.6@2470.27,3410.27 ccw(c2495.07,3435.07) 2495.07,3400 ; P2.0--->P1.7.6@2477.34,3382.66 cw(c2519.21,3340.79) 2519.21,3400 ; P2.0--->P1.7.6@2477.34,3382.66 cw(c2519.21,3340.79) 2519.21,3400 ; P2.0--->P1.7.6@2477.34,3382.66 cw(c2519.21,3340.79) 2519.21,3400 ; P2.0--->P1.7.6@2477.34,3417.34 ccw(c2519.21,3459.21) 2519.21,3400 ; P2.0--->P1.7.6@2477.34,3417.34 ccw(c2519.21,3459.21) 2519.21,3400 ; P2.0--->P1.7.6@2477.34,3417.34 ccw(c2519.21,3459.21) 2519.21,3400
P2_6: P2.0--->P1.7.7 TUSB3210.29 | length 1133.8
  Top Layer w10: P2.0--->P1.7.7@2360,3300 2410,3350 2800,3350 2890.35,3259.65 TUSB3210.29@2890.35,3158.7 ; P2.0--->P1.7.7@2360,3314.53 ccw(c2360,3349.6) 2384.8,3324.8 ; P2.0--->P1.7.7@2360,3314.53 ccw(c2360,3349.6) 2384.8,3324.8 ; P2.0--->P1.7.7@2360,3314.53 ccw(c2360,3349.6) 2384.8,3324.8 ; P2.0--->P1.7.7@2360,3324.53 ccw(c2360,3383.74) 2401.87,3341.87 ; P2.0--->P1.7.7@2360,3324.53 ccw(c2360,3383.74) 2401.87,3341.87 ; P2.0--->P1.7.7@2360,3324.53 ccw(c2360,3383.74) 2401.87,3341.87 ; P2.0--->P1.7.7@2374.53,3300 cw(c2409.6,3300) 2384.8,3324.8 ; P2.0--->P1.7.7@2374.53,3300 cw(c2409.6,3300) 2384.8,3324.8 ; P2.0--->P1.7.7@2374.53,3300 cw(c2409.6,3300) 2384.8,3324.8 ; P2.0--->P1.7.7@2384.53,3300 cw(c2443.74,3300) 2401.87,3341.87 ; P2.0--->P1.7.7@2384.53,3300 cw(c2443.74,3300) 2401.87,3341.87 ; P2.0--->P1.7.7@2384.53,3300 cw(c2443.74,3300) 2401.87,3341.87
P2_7: P2.0--->P1.7.8 TUSB3210.30 | length 963.7
  Top Layer w10: P2.0--->P1.7.8@2460,3300 2815,3300 2870.67,3244.33 TUSB3210.30@2870.67,3158.7 ; P2.0--->P1.7.8@2470.27,3289.73 cw(c2495.07,3264.93) 2495.07,3300 ; P2.0--->P1.7.8@2470.27,3289.73 cw(c2495.07,3264.93) 2495.07,3300 ; P2.0--->P1.7.8@2470.27,3289.73 cw(c2495.07,3264.93) 2495.07,3300 ; P2.0--->P1.7.8@2470.27,3310.27 ccw(c2495.07,3335.07) 2495.07,3300 ; P2.0--->P1.7.8@2470.27,3310.27 ccw(c2495.07,3335.07) 2495.07,3300 ; P2.0--->P1.7.8@2470.27,3310.27 ccw(c2495.07,3335.07) 2495.07,3300 ; P2.0--->P1.7.8@2477.34,3282.66 cw(c2519.21,3240.79) 2519.21,3300 ; P2.0--->P1.7.8@2477.34,3282.66 cw(c2519.21,3240.79) 2519.21,3300 ; P2.0--->P1.7.8@2477.34,3282.66 cw(c2519.21,3240.79) 2519.21,3300 ; P2.0--->P1.7.8@2477.34,3317.34 ccw(c2519.21,3359.21) 2519.21,3300 ; P2.0--->P1.7.8@2477.34,3317.34 ccw(c2519.21,3359.21) 2519.21,3300 ; P2.0--->P1.7.8@2477.34,3317.34 ccw(c2519.21,3359.21) 2519.21,3300
P3_0: MAX3232.9 P0.0---->P3.0.16 TUSB3210.58 | length 1819.6
  Top Layer w10: P0.0---->P3.0.16@2920,2140 2930,2150 2930,2440 3008.46,2518.46 TUSB3210.58@3008.46,2666.57 ; P0.0---->P3.0.16@2902.66,2157.34 ccw(c2836.64,2223.36) 2930,2223.36 ; P0.0---->P3.0.16@2902.66,2157.34 ccw(c2836.64,2223.36) 2930,2223.36 ; P0.0---->P3.0.16@2902.66,2157.34 ccw(c2836.64,2223.36) 2930,2223.36 ; P0.0---->P3.0.16@2909.73,2150.27 ccw(c2860.79,2199.21) 2930,2199.21 ; P0.0---->P3.0.16@2909.73,2150.27 ccw(c2860.79,2199.21) 2930,2199.21 ; P0.0---->P3.0.16@2909.73,2150.27 ccw(c2860.79,2199.21) 2930,2199.21 ; P0.0---->P3.0.16@2916.8,2143.2 ccw(c2884.93,2175.07) 2930,2175.07 ; P0.0---->P3.0.16@2916.8,2143.2 ccw(c2884.93,2175.07) 2930,2175.07 ; P0.0---->P3.0.16@2916.8,2143.2 ccw(c2884.93,2175.07) 2930,2175.07 ; 2930,2175.07 ccw(c2955.07,2175.07) P0.0---->P3.0.16@2937.34,2157.34 ; 2930,2175.07 ccw(c2955.07,2175.07) P0.0---->P3.0.16@2937.34,2157.34 ; 2930,2175.07 ccw(c2955.07,2175.07) P0.0---->P3.0.16@2937.34,2157.34
  Top Layer w20: P0.0---->P3.0.16@2920,2140 MAX3232.9@3480,2140 ; 2967.14,2140 cw(c2967.14,2187.14) 2933.81,2153.81 ccw(c2967.14,2187.14) 2967.14,2140 ; 2967.14,2140 ccw(c2967.14,2092.86) 2933.81,2126.19 cw(c2967.14,2092.86) 2967.14,2140
P3_1: MAX3232.10 P0.0---->P3.0.15 TUSB3210.57 | length 1869.6
  Top Layer w10: P0.0---->P3.0.15@2920,2040 2870,2090 2870,2405 2988.78,2523.78 TUSB3210.57@2988.78,2666.57 ; 2878.13,2081.87 cw(c2836.26,2040) P0.0---->P3.0.15@2895.47,2040 ; 2878.13,2081.87 ccw(c2920,2123.74) P0.0---->P3.0.15@2920,2064.53 ; 2878.13,2081.87 cw(c2836.26,2040) P0.0---->P3.0.15@2895.47,2040 ; 2878.13,2081.87 ccw(c2920,2123.74) P0.0---->P3.0.15@2920,2064.53 ; 2878.13,2081.87 ccw(c2920,2123.74) P0.0---->P3.0.15@2920,2064.53 ; 2878.13,2081.87 cw(c2836.26,2040) P0.0---->P3.0.15@2895.47,2040 ; 2895.2,2064.8 cw(c2870.4,2040) P0.0---->P3.0.15@2905.47,2040 ; 2895.2,2064.8 ccw(c2920,2089.6) P0.0---->P3.0.15@2920,2054.53 ; 2895.2,2064.8 cw(c2870.4,2040) P0.0---->P3.0.15@2905.47,2040 ; 2895.2,2064.8 ccw(c2920,2089.6) P0.0---->P3.0.15@2920,2054.53 ; 2895.2,2064.8 ccw(c2920,2089.6) P0.0---->P3.0.15@2920,2054.53 ; 2895.2,2064.8 cw(c2870.4,2040) P0.0---->P3.0.15@2905.47,2040
  Top Layer w20: P0.0---->P3.0.15@2920,2040 3045,2040 3095,2090 MAX3232.10@3480,2090 ; 2967.14,2040 cw(c2967.14,2087.14) 2933.81,2053.81 ccw(c2967.14,2087.14) 2967.14,2040 ; 2967.14,2040 ccw(c2967.14,1992.86) 2933.81,2026.19 cw(c2967.14,1992.86) 2967.14,2040
P3_2: K4.3 P0.0---->P3.0.14 TUSB3210.56 | length 2602.1
  Top Layer w10: P0.0---->P3.0.14@2820,2140 2820,2385 2969.09,2534.09 TUSB3210.56@2969.09,2666.57 ; P0.0---->P3.0.14@2802.66,2157.34 ccw(c2760.79,2199.21) 2820,2199.21 ; P0.0---->P3.0.14@2802.66,2157.34 ccw(c2760.79,2199.21) 2820,2199.21 ; P0.0---->P3.0.14@2802.66,2157.34 ccw(c2760.79,2199.21) 2820,2199.21 ; P0.0---->P3.0.14@2809.73,2150.27 ccw(c2784.93,2175.07) 2820,2175.07 ; P0.0---->P3.0.14@2809.73,2150.27 ccw(c2784.93,2175.07) 2820,2175.07 ; P0.0---->P3.0.14@2809.73,2150.27 ccw(c2784.93,2175.07) 2820,2175.07 ; 2820,2175.07 ccw(c2855.07,2175.07) P0.0---->P3.0.14@2830.27,2150.27 ; 2820,2175.07 ccw(c2855.07,2175.07) P0.0---->P3.0.14@2830.27,2150.27 ; 2820,2175.07 ccw(c2855.07,2175.07) P0.0---->P3.0.14@2830.27,2150.27 ; 2820,2199.21 ccw(c2879.21,2199.21) P0.0---->P3.0.14@2837.34,2157.34 ; 2820,2199.21 ccw(c2879.21,2199.21) P0.0---->P3.0.14@2837.34,2157.34 ; 2820,2199.21 ccw(c2879.21,2199.21) P0.0---->P3.0.14@2837.34,2157.34
  Bottom Layer w10: P0.0---->P3.0.14@2820,2140 2865,2095 2865,1990 2880,1975 3021,1975 K4.3@3100,1896 ; P0.0---->P3.0.14@2820,2115.47 cw(c2820,2056.26) 2861.87,2098.13 ; P0.0---->P3.0.14@2820,2115.47 cw(c2820,2056.26) 2861.87,2098.13 ; P0.0---->P3.0.14@2820,2115.47 cw(c2820,2056.26) 2861.87,2098.13 ; P0.0---->P3.0.14@2820,2125.47 cw(c2820,2090.4) 2844.8,2115.2 ; P0.0---->P3.0.14@2820,2125.47 cw(c2820,2090.4) 2844.8,2115.2 ; P0.0---->P3.0.14@2820,2125.47 cw(c2820,2090.4) 2844.8,2115.2 ; P0.0---->P3.0.14@2834.53,2140 ccw(c2869.6,2140) 2844.8,2115.2 ; P0.0---->P3.0.14@2834.53,2140 ccw(c2869.6,2140) 2844.8,2115.2 ; P0.0---->P3.0.14@2834.53,2140 ccw(c2869.6,2140) 2844.8,2115.2 ; P0.0---->P3.0.14@2844.53,2140 ccw(c2903.74,2140) 2861.87,2098.13 ; P0.0---->P3.0.14@2844.53,2140 ccw(c2903.74,2140) 2861.87,2098.13 ; P0.0---->P3.0.14@2844.53,2140 ccw(c2903.74,2140) 2861.87,2098.13 ; 3040.25,1955.75 cw(c2980.5,1896) K4.3@3065,1896 ; 3040.25,1955.75 ccw(c3100,2015.5) K4.3@3100,1931 ; 3040.25,1955.75 cw(c2980.5,1896) K4.3@3065,1896 ; 3040.25,1955.75 ccw(c3100,2015.5) K4.3@3100,1931 ; 3040.25,1955.75 ccw(c3100,2015.5) K4.3@3100,1931 ; 3040.25,1955.75 cw(c2980.5,1896) K4.3@3065,1896 ; 3057.32,1938.68 cw(c3014.64,1896) K4.3@3075,1896 ; 3057.32,1938.68 ccw(c3100,1981.36) K4.3@3100,1921 ; 3057.32,1938.68 cw(c3014.64,1896) K4.3@3075,1896 ; 3057.32,1938.68 ccw(c3100,1981.36) K4.3@3100,1921 ; 3057.32,1938.68 ccw(c3100,1981.36) K4.3@3100,1921 ; 3057.32,1938.68 cw(c3014.64,1896) K4.3@3075,1896
P3_3: K3.3 P0.0---->P3.0.13 TUSB3210.55 | length 2188.9
  Top Layer w10: K3.3@2800,1896 2800,1960 ; TUSB3210.55@2949.41,2666.57 2949.41,2544.41 2765,2360 2765,2095 P0.0---->P3.0.13@2820,2040 2820,1980 2800,1960 ; 2778.13,2081.87 cw(c2736.26,2040) P0.0---->P3.0.13@2795.47,2040 ; 2778.13,2081.87 ccw(c2820,2123.74) P0.0---->P3.0.13@2820,2064.53 ; 2778.13,2081.87 cw(c2736.26,2040) P0.0---->P3.0.13@2795.47,2040 ; 2778.13,2081.87 ccw(c2820,2123.74) P0.0---->P3.0.13@2820,2064.53 ; 2778.13,2081.87 ccw(c2820,2123.74) P0.0---->P3.0.13@2820,2064.53 ; 2778.13,2081.87 cw(c2736.26,2040) P0.0---->P3.0.13@2795.47,2040 ; K3.3@2781.12,1925.47 ccw(c2758.99,1960) 2800,1960 ; K3.3@2781.12,1925.47 ccw(c2758.99,1960) 2800,1960 ; K3.3@2781.12,1925.47 ccw(c2758.99,1960) 2800,1960 ; K3.3@2786.51,1917.05 ccw(c2770.71,1941.71) 2800,1941.71 ; K3.3@2786.51,1917.05 ccw(c2770.71,1941.71) 2800,1941.71 ; K3.3@2786.51,1917.05 ccw(c2770.71,1941.71) 2800,1941.71 ; 2795.2,2064.8 cw(c2770.4,2040) P0.0---->P3.0.13@2805.47,2040 ; 2795.2,2064.8 ccw(c2820,2089.6) P0.0---->P3.0.13@2820,2054.53 ; 2795.2,2064.8 cw(c2770.4,2040) P0.0---->P3.0.13@2805.47,2040 ; 2795.2,2064.8 ccw(c2820,2089.6) P0.0---->P3.0.13@2820,2054.53 ; 2795.2,2064.8 ccw(c2820,2089.6) P0.0---->P3.0.13@2820,2054.53 ; 2795.2,2064.8 cw(c2770.4,2040) P0.0---->P3.0.13@2805.47,2040 ; 2800,1941.71 ccw(c2829.29,1941.71) K3.3@2813.49,1917.05 ; 2800,1941.71 ccw(c2829.29,1941.71) K3.3@2813.49,1917.05 ; 2800,1941.71 ccw(c2829.29,1941.71) K3.3@2813.49,1917.05 ; 2800,1960 ccw(c2841.01,1960) K3.3@2818.88,1925.47 ; 2800,1960 ccw(c2841.01,1960) K3.3@2818.88,1925.47 ; 2800,1960 ccw(c2841.01,1960) K3.3@2818.88,1925.47 ; P0.0---->P3.0.13@2802.66,2022.66 cw(c2760.79,1980.79) 2820,1980.79 ; P0.0---->P3.0.13@2802.66,2022.66 cw(c2760.79,1980.79) 2820,1980.79 ; P0.0---->P3.0.13@2802.66,2022.66 cw(c2760.79,1980.79) 2820,1980.79 ; P0.0---->P3.0.13@2809.73,2029.73 cw(c2784.93,2004.93) 2820,2004.93 ; P0.0---->P3.0.13@2809.73,2029.73 cw(c2784.93,2004.93) 2820,2004.93 ; P0.0---->P3.0.13@2809.73,2029.73 cw(c2784.93,2004.93) 2820,2004.93 ; 2820,1980.79 cw(c2879.21,1980.79) P0.0---->P3.0.13@2837.34,2022.66 ; 2820,1980.79 cw(c2879.21,1980.79) P0.0---->P3.0.13@2837.34,2022.66 ; 2820,1980.79 cw(c2879.21,1980.79) P0.0---->P3.0.13@2837.34,2022.66 ; 2820,2004.93 cw(c2855.07,2004.93) P0.0---->P3.0.13@2830.27,2029.73 ; 2820,2004.93 cw(c2855.07,2004.93) P0.0---->P3.0.13@2830.27,2029.73 ; 2820,2004.93 cw(c2855.07,2004.93) P0.0---->P3.0.13@2830.27,2029.73
P3_4: K2.3 P0.0---->P3.0.12 TUSB3210.54 | length 2535.5
  Top Layer w10: P0.0---->P3.0.12@2720,2140 2720,2340 2929.72,2549.72 TUSB3210.54@2929.72,2666.57 ; P0.0---->P3.0.12@2702.66,2157.34 ccw(c2660.79,2199.21) 2720,2199.21 ; P0.0---->P3.0.12@2702.66,2157.34 ccw(c2660.79,2199.21) 2720,2199.21 ; P0.0---->P3.0.12@2702.66,2157.34 ccw(c2660.79,2199.21) 2720,2199.21 ; P0.0---->P3.0.12@2709.73,2150.27 ccw(c2684.93,2175.07) 2720,2175.07 ; P0.0---->P3.0.12@2709.73,2150.27 ccw(c2684.93,2175.07) 2720,2175.07 ; P0.0---->P3.0.12@2709.73,2150.27 ccw(c2684.93,2175.07) 2720,2175.07 ; 2720,2175.07 ccw(c2755.07,2175.07) P0.0---->P3.0.12@2730.27,2150.27 ; 2720,2175.07 ccw(c2755.07,2175.07) P0.0---->P3.0.12@2730.27,2150.27 ; 2720,2175.07 ccw(c2755.07,2175.07) P0.0---->P3.0.12@2730.27,2150.27 ; 2720,2199.21 ccw(c2779.21,2199.21) P0.0---->P3.0.12@2737.34,2157.34 ; 2720,2199.21 ccw(c2779.21,2199.21) P0.0---->P3.0.12@2737.34,2157.34 ; 2720,2199.21 ccw(c2779.21,2199.21) P0.0---->P3.0.12@2737.34,2157.34
  Bottom Layer w10: K2.3@2520,1896 2594,1970 2635,1970 2670,2005 2670,2090 P0.0---->P3.0.12@2720,2140 ; K2.3@2520,1921 ccw(c2520,1981.36) 2562.68,1938.68 ; K2.3@2520,1921 ccw(c2520,1981.36) 2562.68,1938.68 ; K2.3@2520,1921 ccw(c2520,1981.36) 2562.68,1938.68 ; K2.3@2520,1931 ccw(c2520,2015.5) 2579.75,1955.75 ; K2.3@2520,1931 ccw(c2520,2015.5) 2579.75,1955.75 ; K2.3@2520,1931 ccw(c2520,2015.5) 2579.75,1955.75 ; K2.3@2545,1896 cw(c2605.36,1896) 2562.68,1938.68 ; K2.3@2545,1896 cw(c2605.36,1896) 2562.68,1938.68 ; K2.3@2545,1896 cw(c2605.36,1896) 2562.68,1938.68 ; K2.3@2555,1896 cw(c2639.5,1896) 2579.75,1955.75 ; K2.3@2555,1896 cw(c2639.5,1896) 2579.75,1955.75 ; K2.3@2555,1896 cw(c2639.5,1896) 2579.75,1955.75 ; 2678.13,2098.13 cw(c2720,2056.26) P0.0---->P3.0.12@2720,2115.47 ; 2678.13,2098.13 ccw(c2636.26,2140) P0.0---->P3.0.12@2695.47,2140 ; 2678.13,2098.13 cw(c2720,2056.26) P0.0---->P3.0.12@2720,2115.47 ; 2678.13,2098.13 ccw(c2636.26,2140) P0.0---->P3.0.12@2695.47,2140 ; 2678.13,2098.13 ccw(c2636.26,2140) P0.0---->P3.0.12@2695.47,2140 ; 2678.13,2098.13 cw(c2720,2056.26) P0.0---->P3.0.12@2720,2115.47 ; 2695.2,2115.2 cw(c2720,2090.4) P0.0---->P3.0.12@2720,2125.47 ; 2695.2,2115.2 ccw(c2670.4,2140) P0.0---->P3.0.12@2705.47,2140 ; 2695.2,2115.2 cw(c2720,2090.4) P0.0---->P3.0.12@2720,2125.47 ; 2695.2,2115.2 ccw(c2670.4,2140) P0.0---->P3.0.12@2705.47,2140 ; 2695.2,2115.2 ccw(c2670.4,2140) P0.0---->P3.0.12@2705.47,2140 ; 2695.2,2115.2 cw(c2720,2090.4) P0.0---->P3.0.12@2720,2125.47
P3_5: K1.3 P0.0---->P3.0.11 TUSB3210.53 | length 2853.5
  Top Layer w10: K1.3@2240,1896 2309,1965 2645,1965 P0.0---->P3.0.11@2720,2040 2675,2085 2675,2330 2910.04,2565.04 TUSB3210.53@2910.04,2666.57 ; K1.3@2240,1921 ccw(c2240,1981.36) 2282.68,1938.68 ; K1.3@2240,1921 ccw(c2240,1981.36) 2282.68,1938.68 ; K1.3@2240,1921 ccw(c2240,1981.36) 2282.68,1938.68 ; K1.3@2240,1931 ccw(c2240,2015.5) 2299.75,1955.75 ; K1.3@2240,1931 ccw(c2240,2015.5) 2299.75,1955.75 ; K1.3@2240,1931 ccw(c2240,2015.5) 2299.75,1955.75 ; K1.3@2265,1896 cw(c2325.36,1896) 2282.68,1938.68 ; K1.3@2265,1896 cw(c2325.36,1896) 2282.68,1938.68 ; K1.3@2265,1896 cw(c2325.36,1896) 2282.68,1938.68 ; K1.3@2275,1896 cw(c2359.5,1896) 2299.75,1955.75 ; K1.3@2275,1896 cw(c2359.5,1896) 2299.75,1955.75 ; K1.3@2275,1896 cw(c2359.5,1896) 2299.75,1955.75 ; 2678.13,1998.13 cw(c2720,1956.26) P0.0---->P3.0.11@2720,2015.47 ; 2678.13,1998.13 ccw(c2636.26,2040) P0.0---->P3.0.11@2695.47,2040 ; 2678.13,1998.13 cw(c2720,1956.26) P0.0---->P3.0.11@2720,2015.47 ; 2678.13,1998.13 ccw(c2636.26,2040) P0.0---->P3.0.11@2695.47,2040 ; 2678.13,1998.13 ccw(c2636.26,2040) P0.0---->P3.0.11@2695.47,2040 ; 2678.13,1998.13 cw(c2720,1956.26) P0.0---->P3.0.11@2720,2015.47 ; 2678.13,2081.87 cw(c2636.26,2040) P0.0---->P3.0.11@2695.47,2040 ; 2678.13,2081.87 ccw(c2720,2123.74) P0.0---->P3.0.11@2720,2064.53 ; 2678.13,2081.87 cw(c2636.26,2040) P0.0---->P3.0.11@2695.47,2040 ; 2678.13,2081.87 ccw(c2720,2123.74) P0.0---->P3.0.11@2720,2064.53 ; 2678.13,2081.87 ccw(c2720,2123.74) P0.0---->P3.0.11@2720,2064.53 ; 2678.13,2081.87 cw(c2636.26,2040) P0.0---->P3.0.11@2695.47,2040 ; 2695.2,2015.2 cw(c2720,1990.4) P0.0---->P3.0.11@2720,2025.47 ; 2695.2,2015.2 ccw(c2670.4,2040) P0.0---->P3.0.11@2705.47,2040 ; 2695.2,2015.2 cw(c2720,1990.4) P0.0---->P3.0.11@2720,2025.47 ; 2695.2,2015.2 ccw(c2670.4,2040) P0.0---->P3.0.11@2705.47,2040 ; 2695.2,2015.2 ccw(c2670.4,2040) P0.0---->P3.0.11@2705.47,2040 ; 2695.2,2015.2 cw(c2720,1990.4) P0.0---->P3.0.11@2720,2025.47 ; 2695.2,2064.8 cw(c2670.4,2040) P0.0---->P3.0.11@2705.47,2040 ; 2695.2,2064.8 ccw(c2720,2089.6) P0.0---->P3.0.11@2720,2054.53 ; 2695.2,2064.8 cw(c2670.4,2040) P0.0---->P3.0.11@2705.47,2040 ; 2695.2,2064.8 ccw(c2720,2089.6) P0.0---->P3.0.11@2720,2054.53 ; 2695.2,2064.8 ccw(c2720,2089.6) P0.0---->P3.0.11@2720,2054.53 ; 2695.2,2064.8 cw(c2670.4,2040) P0.0---->P3.0.11@2705.47,2040
P3_6: P0.0---->P3.0.10 TUSB3210.52 | length 1082.9
  Top Layer w10: P0.0---->P3.0.10@2620,2140 2620,2300 2890.35,2570.35 TUSB3210.52@2890.35,2666.57 ; P0.0---->P3.0.10@2602.66,2157.34 ccw(c2560.79,2199.21) 2620,2199.21 ; P0.0---->P3.0.10@2602.66,2157.34 ccw(c2560.79,2199.21) 2620,2199.21 ; P0.0---->P3.0.10@2602.66,2157.34 ccw(c2560.79,2199.21) 2620,2199.21 ; P0.0---->P3.0.10@2609.73,2150.27 ccw(c2584.93,2175.07) 2620,2175.07 ; P0.0---->P3.0.10@2609.73,2150.27 ccw(c2584.93,2175.07) 2620,2175.07 ; P0.0---->P3.0.10@2609.73,2150.27 ccw(c2584.93,2175.07) 2620,2175.07 ; 2620,2175.07 ccw(c2655.07,2175.07) P0.0---->P3.0.10@2630.27,2150.27 ; 2620,2175.07 ccw(c2655.07,2175.07) P0.0---->P3.0.10@2630.27,2150.27 ; 2620,2175.07 ccw(c2655.07,2175.07) P0.0---->P3.0.10@2630.27,2150.27 ; 2620,2199.21 ccw(c2679.21,2199.21) P0.0---->P3.0.10@2637.34,2157.34 ; 2620,2199.21 ccw(c2679.21,2199.21) P0.0---->P3.0.10@2637.34,2157.34 ; 2620,2199.21 ccw(c2679.21,2199.21) P0.0---->P3.0.10@2637.34,2157.34
P3_7: P0.0---->P3.0.9 TUSB3210.51 | length 1216.1
  Top Layer w10: P0.0---->P3.0.9@2620,2040 2570,2090 2570,2275 2870.67,2575.67 TUSB3210.51@2870.67,2666.57 ; 2578.13,2081.87 cw(c2536.26,2040) P0.0---->P3.0.9@2595.47,2040 ; 2578.13,2081.87 ccw(c2620,2123.74) P0.0---->P3.0.9@2620,2064.53 ; 2578.13,2081.87 cw(c2536.26,2040) P0.0---->P3.0.9@2595.47,2040 ; 2578.13,2081.87 ccw(c2620,2123.74) P0.0---->P3.0.9@2620,2064.53 ; 2578.13,2081.87 ccw(c2620,2123.74) P0.0---->P3.0.9@2620,2064.53 ; 2578.13,2081.87 cw(c2536.26,2040) P0.0---->P3.0.9@2595.47,2040 ; 2595.2,2064.8 cw(c2570.4,2040) P0.0---->P3.0.9@2605.47,2040 ; 2595.2,2064.8 ccw(c2620,2089.6) P0.0---->P3.0.9@2620,2054.53 ; 2595.2,2064.8 cw(c2570.4,2040) P0.0---->P3.0.9@2605.47,2040 ; 2595.2,2064.8 ccw(c2620,2089.6) P0.0---->P3.0.9@2620,2054.53 ; 2595.2,2064.8 ccw(c2620,2089.6) P0.0---->P3.0.9@2620,2054.53 ; 2595.2,2064.8 cw(c2570.4,2040) P0.0---->P3.0.9@2605.47,2040
RST_TUSB: C11.1 R10.1 R11.2 TUSB3210.13 | length 2087
  Top Layer w10: TUSB3210.13@3225,3001.22 3291.22,3001.22 3315,3025 3480,3025 v1(3695,2810) ; v1@3685,2810 ccw(c3660.86,2810) 3677.93,2827.07 ccw(c3695,2844.14) v1@3695,2820
  Bottom Layer w10: v1(3695,2810) 4390,2810 4520,2940 R11.2@4520,3021.61 ; v1@3702.07,2802.93 cw(c3719.14,2785.86) 3719.14,2810 cw(c3719.14,2834.14) v1@3702.07,2817.07 ; R11.2@4505.44,3006.07 cw(c4470.29,2970.92) 4520,2970.92 cw(c4569.71,2970.92) R11.2@4534.56,3006.07
  Bottom Layer w30: R10.1@4285,2963.39 4285,3025 ; C11.1@4285,3086.61 4285,3025 ; 4476.56,3030 cw(c4476.56,2979.16) R11.2@4512.51,3015.11 ; R11.2@4520,3021.61 4511.61,3030 4290,3030 4285,3025
SCL: AT24CXX.6 R18.1 TUSB3210.12 | length 1165.2
  Top Layer w10: TUSB3210.12@3225,2981.53 3321.53,2981.53 v1(3325,2985) ; 3292.49,2981.53 ccw(c3292.49,3017.51) v1@3317.93,2992.07 ; 3309.22,2981.54 cw(c3309.22,2969.22) v1@3317.93,2977.93
  Bottom Layer w10: v1@3317.93,2977.93 cw(c3300.86,2960.86) 3325,2960.86 cw(c3349.14,2960.86) v1@3332.07,2977.93 ; v1(3325,2985) 3325,2695 AT24CXX.6@3495,2525 ; AT24CXX.6@3470.47,2525 ccw(c3411.26,2525) 3453.13,2566.87 ccw(c3495,2608.74) AT24CXX.6@3495,2549.53 ; AT24CXX.6@3480.47,2525 ccw(c3445.4,2525) 3470.2,2549.8 ccw(c3495,2574.6) AT24CXX.6@3495,2539.53
  Bottom Layer w30: AT24CXX.6@3495,2525 3596.61,2525 R18.1@3621.61,2500 ; AT24CXX.6@3505.27,2514.73 cw(c3530.07,2489.93) 3530.07,2525 cw(c3530.07,2560.07) AT24CXX.6@3505.27,2535.27 ; 3534.71,2525 cw(c3534.71,2414.08) R18.1@3613.14,2492.51 ; R18.1@3607.13,2525 cw(c3607.13,2486.5) R18.1@3634.35,2513.72
SDA: AT24CXX.5 R19.1 TUSB3210.11 | length 976.7
  Top Layer w10: TUSB3210.11@3225,2961.85 3293.15,2961.85 3305,2950 v1(3385,2950) ; v1@3377.93,2942.93 ccw(c3360.86,2925.86) 3360.86,2950 ccw(c3360.86,2974.14) v1@3377.93,2957.07
  Bottom Layer w10: v1@3377.93,2942.93 cw(c3360.86,2925.86) 3385,2925.86 cw(c3409.14,2925.86) v1@3392.07,2942.93 ; v1(3385,2950) 3385,2735 AT24CXX.5@3495,2625 ; AT24CXX.5@3470.47,2625 ccw(c3411.26,2625) 3453.13,2666.87 ccw(c3495,2708.74) AT24CXX.5@3495,2649.53 ; AT24CXX.5@3480.47,2625 ccw(c3445.4,2625) 3470.2,2649.8 ccw(c3495,2674.6) AT24CXX.5@3495,2639.53
  Bottom Layer w30: AT24CXX.5@3495,2625 3616.61,2625 R19.1@3621.61,2620 ; AT24CXX.5@3505.27,2614.73 cw(c3530.07,2589.93) 3530.07,2625 cw(c3530.07,2660.07) AT24CXX.5@3505.27,2635.27 ; 3582.99,2625 cw(c3582.99,2582.36) R19.1@3613.14,2612.51
SUSP: R14.1 SUSP.2 TUSB3210.16 TUSB3210.38 | length 1936.3
  Top Layer w10: v1(2655,2965) 2658.15,2961.85 TUSB3210.38@2732.87,2961.85 3058.06,2961.85 3156.49,3060.28 TUSB3210.16@3225,3060.28 3545.28,3060.28 v1(3575,3090) ; v1@2662.07,2957.93 cw(c2671.54,2948.46) 2671.54,2961.85 ; v1@2662.07,2972.07 ccw(c2686.75,2996.75) TUSB3210.38@2686.75,2961.85 ; v1@3565,3090 cw(c3540.86,3090) 3557.93,3072.93 cw(c3575,3055.86) v1@3575,3080
  Bottom Layer w10: v1(3575,3090) 3820,3335 4130,3335 ; v1@3575,3100 ccw(c3575,3124.14) 3592.07,3107.07 ccw(c3609.14,3090) v1@3585,3090 ; SUSP.2@4144.08,3373.02 cw(c4095.68,3369.32) 4130,3335 ; SUSP.2@4154.05,3373.78 cw(c4124.27,3371.5) 4145.39,3350.39 cw(c4166.5,3329.27) SUSP.2@4168.78,3359.05 ; SUSP.2@4168.02,3349.08 ccw(c4164.32,3300.68) 4130,3335 ; SUSP.2@4170,3375 4130,3335
VBUS: AS1117-3.3.3 C1.2 C2.2 J1.1 R13.2 | length 2062
  Top Layer w30: J1.1@2955,3630 3015,3690 3244.84,3690 3344.84,3590 3520,3590 3651.61,3458.39 3759.45,3350.55 AS1117-3.3.3@3759.45,3047.05 ; J1.1@2955,3647.5 ccw(c2955,3689.75) 2984.87,3659.87 ccw(c3014.75,3630) J1.1@2972.5,3630 ; 3735.92,3374.08 cw(c3701.85,3340) C1.2@3750.04,3340 ; 3759.45,3311.58 cw(c3789.05,3311.58) C1.2@3768.12,3332.51
  Bottom Layer w30: C2.2@2680,3590.04 cw(c2680,3562.09) C2.2@2699.76,3581.85 ; C2.2@2680,3601.61 2793.23,3488.39 R13.2@2915,3488.39 2915,3590 J1.1@2955,3630 ; 2925.13,3600.13 cw(c2955,3570.25) J1.1@2955,3612.5 ; 2925.13,3600.13 ccw(c2895.25,3630) J1.1@2937.5,3630 ; 2925.13,3600.13 cw(c2955,3570.25) J1.1@2955,3612.5 ; 2925.13,3600.13 ccw(c2895.25,3630) J1.1@2937.5,3630 ; 2925.13,3600.13 ccw(c2895.25,3630) J1.1@2937.5,3630 ; 2925.13,3600.13 cw(c2955,3570.25) J1.1@2955,3612.5
pads on no net: AT24CXX.7 JP_COM1.1 JP_COM1.4 JP_COM1.6 JP_COM1.7 JP_COM1.8 JP_COM1.9 K1.1 K1.4 K2.1 K2.4 K3.1 K3.4 K4.1 K4.4 MAX3232.11 MAX3232.12 MAX3232.13 MAX3232.14 SW1.1 SW1.4 TUSB3210.1 TUSB3210.2 TUSB3210.3 TUSB3210.4 TUSB3210.6 TUSB3210.7 TUSB3210.14 TUSB3210.15 TUSB3210.20 TUSB3210.63 TUSB3210.64

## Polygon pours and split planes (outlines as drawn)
GND on Top Layer "1" (hatched 90Degree grid 20 track 8, remove dead copper, pour order 1000): 1705,3840 1705,1575 4740,1575 4740,3840 1705,3840
GND on Bottom Layer "2" (hatched 90Degree grid 20 track 8, remove dead copper, pour order 1001): 1705,3840 1705,1575 4740,1575 4740,3840

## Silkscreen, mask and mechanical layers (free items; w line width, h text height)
Top Overlay:
  text "Design" at 3845,2655 h60
  text "By KKK" at 3850,2520 h60
  text "20100417" at 3845,2420 h50
  text "http://bbs.dspoz.com/" at 2215,2360 h70 r90
Mechanical 1:
  lines w10: 1705,1575 4740,1575 4740,3840 1705,3840 1705,1575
